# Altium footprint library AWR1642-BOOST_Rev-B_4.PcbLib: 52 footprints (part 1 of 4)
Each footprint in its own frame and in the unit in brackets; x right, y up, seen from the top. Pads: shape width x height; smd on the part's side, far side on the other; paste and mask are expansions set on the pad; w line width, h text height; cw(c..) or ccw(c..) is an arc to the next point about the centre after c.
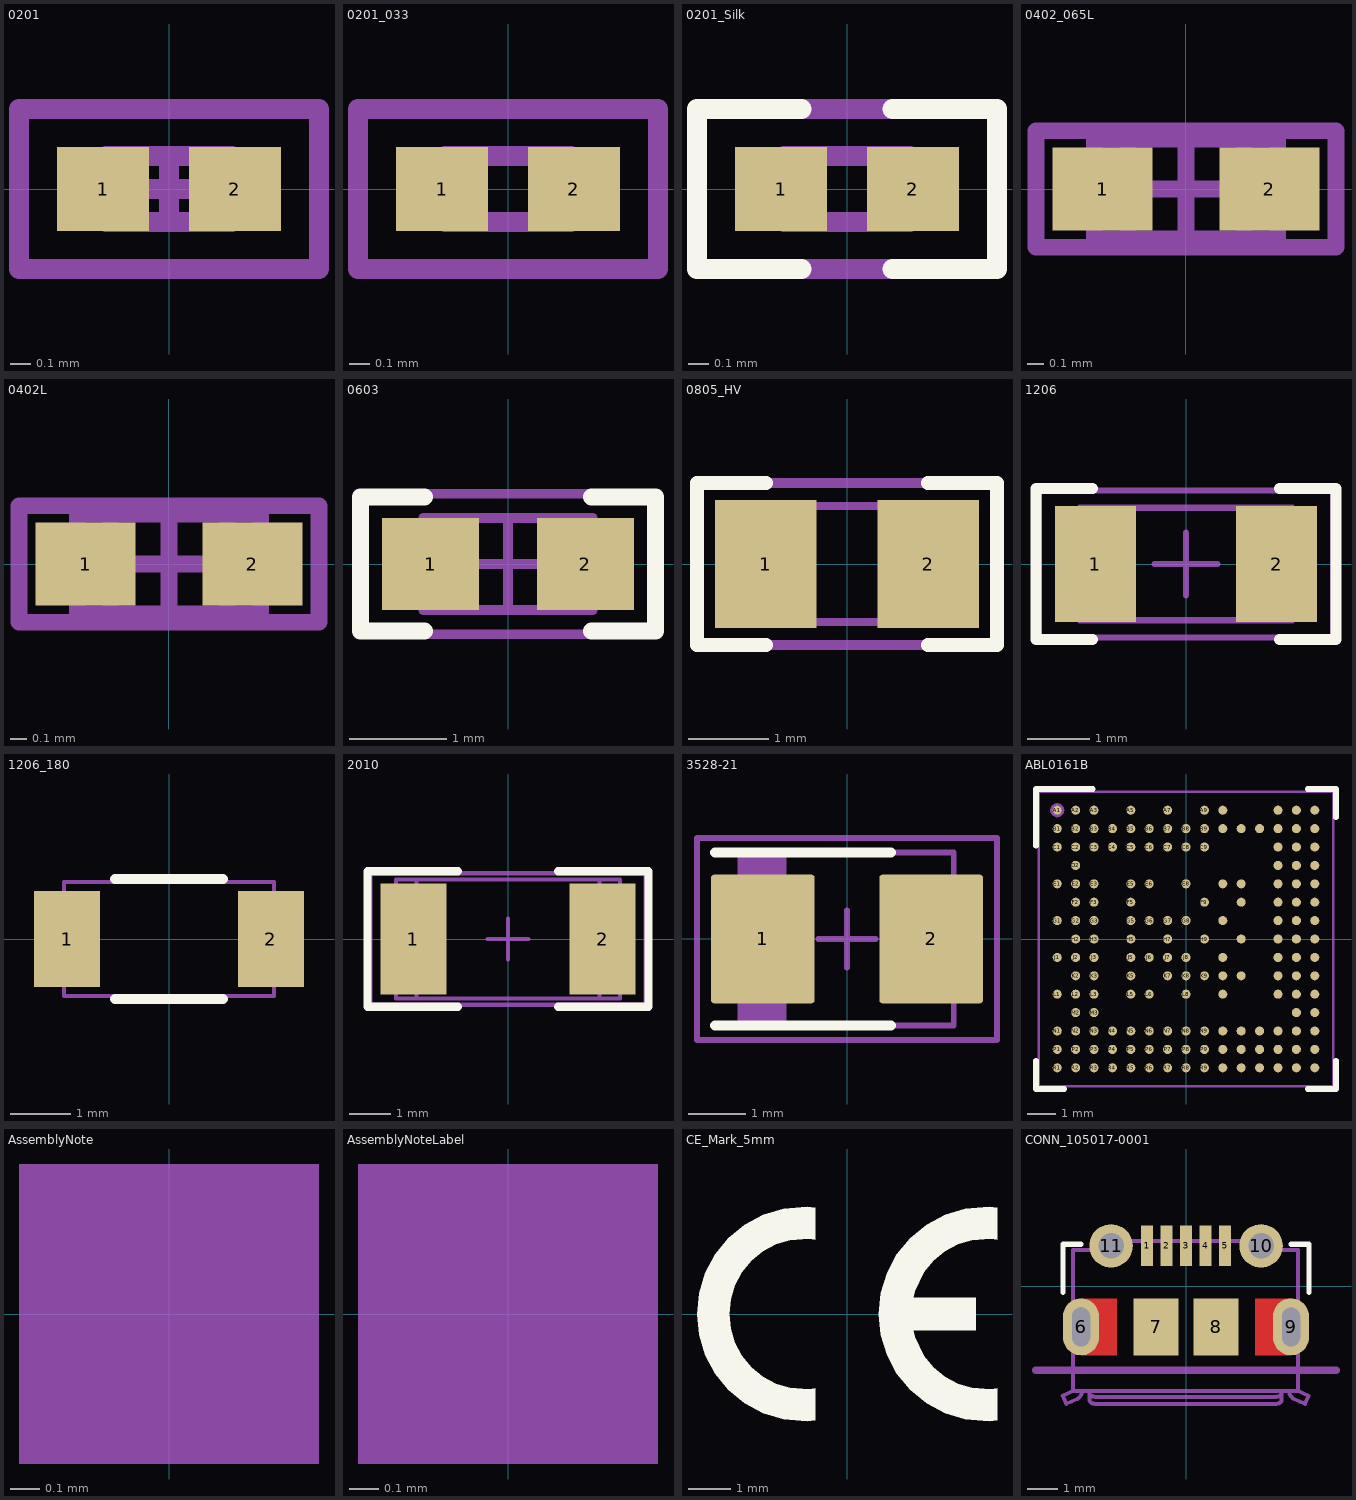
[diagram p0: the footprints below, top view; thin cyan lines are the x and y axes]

## 0201 [mm] "Data from Kemet datasheet CC101_COM dated 7/28/11"
height 0.26
pads (2):
  rect 0.46x0.42 smd mask+0.048: 1(-0.33,0) 2(0.33,0)
Mechanical 5:
  lines w0.1: -0.75,-0.4 -0.75,0.4 0.75,0.4 0.75,-0.4 -0.75,-0.4
  text ".Designator" at -0.66,-0.178 h0.36
Mechanical 13:
  lines w0.1: -0.215,-0.165 -0.215,0.165 ; 0.215,-0.165 0.215,0.165 ; -0.315,-0.165 0.315,-0.165 0.315,0.165 -0.315,0.165 -0.315,-0.165
Mechanical 15:
  lines w0.1: -0.165,0 0.165,0 ; 0,-0.165 0,0.165 ; -0.75,-0.4 0.75,-0.4 0.75,0.4 -0.75,0.4 -0.75,-0.4
3D body: height 0.26, standoff 0, extent 0.216,-0.164 0.314,0.164
3D body: height 0.26, standoff 0, extent -0.214,-0.164 0.214,0.164
3D body: height 0.26, standoff 0, extent -0.314,-0.164 -0.216,0.164

## 0201_033 [mm] "SMD, 2-Leads, Height 0.33mm"
height 0.33
pads (2):
  rect 0.46x0.42 smd mask+0: 1(-0.33,0) 2(0.33,0)
Mechanical 5:
  lines w0.1: -0.75,-0.4 -0.75,0.4 0.75,0.4 0.75,-0.4 -0.75,-0.4
  text ".Designator" at 0.644,0.219 h0.36
Mechanical 13:
  lines w0.1: -0.215,-0.165 -0.215,0.165 ; 0.215,-0.165 0.215,0.165 ; -0.315,-0.165 0.315,-0.165 0.315,0.165 -0.315,0.165 -0.315,-0.165
3D body: height 0.33, standoff 0, extent 0.216,-0.164 0.314,0.164
3D body: height 0.33, standoff 0, extent -0.214,-0.164 0.214,0.164
3D body: height 0.33, standoff 0, extent -0.314,-0.164 -0.216,0.164

## 0201_Silk [mm] "Data from Kemet datasheet CC101_COM dated 7/28/11"
height 0.26
pads (2):
  rect 0.46x0.42 smd mask+0: 1(-0.33,0) 2(0.33,0)
Top Overlay:
  lines w0.1: -0.229,-0.4 -0.75,-0.4 -0.75,0.4 -0.229,0.4 ; 0.229,-0.4 0.75,-0.4 0.75,0.4 0.229,0.4
Mechanical 5:
  lines w0.1: -0.75,-0.4 0.75,-0.4 0.75,0.4 -0.75,0.4 -0.75,-0.4
  text ".Designator" at 0.44,0.181 h0.36
Mechanical 13:
  lines w0.1: -0.215,-0.165 -0.215,0.165 ; 0.215,-0.165 0.215,0.165 ; -0.315,-0.165 -0.315,0.165 0.315,0.165 0.315,-0.165 -0.315,-0.165
3D body: height 0.26, standoff 0, extent -0.314,-0.164 -0.216,0.164
3D body: height 0.26, standoff 0, extent -0.214,-0.164 0.214,0.164
3D body: height 0.26, standoff 0, extent 0.216,-0.164 0.314,0.164

## 0402_065L [mm] "0402"
height 0.65
pads (2):
  rect 0.6x0.5 smd: 1(-0.5,0) 2(0.5,0)
Mechanical 5:
  lines w0.1: -0.9,-0.35 0.9,-0.35 0.9,0.35 -0.9,0.35 -0.9,-0.35
  text ".Designator" at 0.612,0.199 h0.43
Mechanical 13:
  lines w0.1: -0.35,-0.3 -0.35,0.3 ; 0.35,-0.3 0.35,0.3 ; -0.55,-0.3 -0.55,0.3 0.55,0.3 0.55,-0.3 -0.55,-0.3
Mechanical 15:
  lines w0.1: -0.3,0 0.3,0 ; 0,-0.3 0,0.3 ; -0.9,-0.35 -0.9,0.35 0.9,0.35 0.9,-0.35 -0.9,-0.35
3D body: height 0.65, standoff 0, extent -0.549,-0.299 -0.351,0.299
3D body: height 0.65, standoff 0, extent -0.349,-0.299 0.349,0.299
3D body: height 0.65, standoff 0, extent 0.351,-0.299 0.549,0.299

## 0402L [mm] "0402 from SM-752 data"
height 0.6
pads (2):
  rect 0.6x0.5 smd: 1(-0.5,0) 2(0.5,0)
Mechanical 5:
  lines w0.1: -0.9,-0.35 -0.9,0.35 0.9,0.35 0.9,-0.35 -0.9,-0.35
  text ".Designator" at -0.775,-0.225 h0.43
Mechanical 13:
  lines w0.1: -0.35,-0.3 -0.35,0.3 ; 0.35,-0.3 0.35,0.3 ; -0.55,-0.3 0.55,-0.3 0.55,0.3 -0.55,0.3 -0.55,-0.3
Mechanical 15:
  lines w0.1: -0.3,0 0.3,0 ; 0,-0.3 0,0.3 ; -0.9,-0.35 0.9,-0.35 0.9,0.35 -0.9,0.35 -0.9,-0.35
3D body: height 0.6, standoff 0, extent 0.351,-0.299 0.549,0.299
3D body: height 0.6, standoff 0, extent -0.349,-0.299 0.349,0.299
3D body: height 0.6, standoff 0, extent -0.549,-0.299 -0.351,0.299

## 0603 [mm] "0603 from SM-752 data"
height 1
pads (2):
  rect 1x0.95 smd: 1(-0.8,0) 2(0.8,0)
Top Overlay:
  lines w0.178: -0.864,-0.691 -1.524,-0.691 -1.524,0.693 -0.864,0.693 ; 0.864,-0.691 1.524,-0.691 1.524,0.693 0.864,0.693
Mechanical 5:
  lines w0.1: -1.55,-0.725 -1.55,0.725 1.55,0.725 1.55,-0.725 -1.55,-0.725
  text ".Designator" at -1.081,-0.401 h0.76
Mechanical 13:
  lines w0.1: -0.55,-0.475 -0.55,0.475 ; 0.55,-0.475 0.55,0.475 ; -0.875,-0.475 0.875,-0.475 0.875,0.475 -0.875,0.475 -0.875,-0.475
Mechanical 15:
  lines w0.1: -0.475,0 0.475,0 ; 0,-0.475 0,0.475 ; -1.55,-0.725 1.55,-0.725 1.55,0.725 -1.55,0.725 -1.55,-0.725
3D body: height 1, standoff 0, extent -0.874,-0.474 -0.551,0.474
3D body: height 1, standoff 0, extent -0.549,-0.474 0.549,0.474
3D body: height 1, standoff 0, extent 0.551,-0.474 0.874,0.474

## 0805_HV [mil] "0805 with 30mil clearance between pads"
height 57.09
pads (2):
  rect 50x63 smd: 1(-40,0) 2(40,0)
Top Overlay:
  lines w7: -40,-40 -74,-40 -74,0 -74,40 -40,40 ; 40,-40 74,-40 74,0 74,40 40,40
Mechanical 5:
  lines w5: -74,-40 74,-40 74,40 -74,40 -74,-40
  text ".Designator" at 33.84,16.51 h35
Mechanical 13:
  lines w3.94: -25.59,-28.54 -25.59,28.54 ; 25.59,-28.54 25.59,28.54 ; -43.31,-28.54 43.31,-28.54 43.31,28.54 -43.31,28.54 -43.31,-28.54
3D body: height 57.09, standoff 0, extent -43.29,-28.52 -25.61,28.52
3D body: height 57.09, standoff 0, extent -25.57,-28.52 25.57,28.52
3D body: height 57.09, standoff 0, extent 25.61,-28.52 43.29,28.52

## 1206 [mm] "1206 from SM-752 data"
height 1.35
pads (2):
  rect 1.3x1.85 smd: 1(-1.45,0) 2(1.45,0)
Top Overlay:
  lines w0.178: -1.5,-1.21 -2.4,-1.21 -2.4,1.21 -1.5,1.21 ; 1.5,-1.21 2.4,-1.21 2.4,1.21 1.5,1.21
Mechanical 5:
  lines w0.1: -1.7,-0.9 -1.7,0.9 1.7,0.9 1.7,-0.9 -1.7,-0.9
  text ".Designator" at 0.548,0.416 h0.81
Mechanical 13:
  lines w0.1: -1.2,-0.9 -1.2,0.9 ; 1.2,-0.9 1.2,0.9 ; -1.7,-0.9 -1.7,0.9 1.7,0.9 1.7,-0.9 -1.7,-0.9
Mechanical 15:
  lines w0.1: -0.5,0 0.5,0 ; 0,-0.5 0,0.5 ; -2.35,-1.175 -2.35,1.175 2.35,1.175 2.35,-1.175 -2.35,-1.175
3D body: height 1.35, standoff 0, extent 1.201,-0.899 1.699,0.899
3D body: height 1.35, standoff 0, extent -1.199,-0.899 1.199,0.899
3D body: height 1.35, standoff 0, extent -1.699,-0.899 -1.201,0.899

## 1206_180 [mm] "1206_180"
height 1.8
pads (2):
  rect 1.1x1.6 smd: 1(-1.7,0) 2(1.7,0)
Top Overlay:
  lines w0.17: -0.9,-1 0.9,-1 ; -0.9,1 0.9,1
Mechanical 5:
  lines w0.07: -1.75,-0.95 1.75,-0.95 1.75,0.95 -1.75,0.95 -1.75,-0.95
  text ".Designator" at 1.04,0.497 h0.81
3D body: height 1.8, standoff 0, extent -1.749,-0.949 -1.301,0.949
3D body: height 1.8, standoff 0, extent -1.299,-0.949 1.299,0.949
3D body: height 1.8, standoff 0, extent 1.301,-0.949 1.749,0.949

## 2010 [mm] "Chip Capacitor, Body 5.08x2.54mm, IPC Medium Density"
height 1.66
pads (2):
  rect 1.6x2.7 smd: 1(-2.3,0) 2(2.3,0)
Top Overlay:
  lines w0.2: -1.219,-1.65 -3.419,-1.65 -3.419,1.65 -1.219,1.65 ; 1.219,-1.65 3.419,-1.65 3.419,1.65 1.219,1.65
Mechanical 5:
  lines w0.1: -2.73,-1.45 2.73,-1.45 2.73,1.45 -2.73,1.45 -2.73,-1.45
  text ".Designator" at -1.875,-0.5 h1.02
Mechanical 13:
  lines w0.1: -2.23,-1.45 -2.23,1.45 ; 2.23,-1.45 2.23,1.45 ; -2.73,-1.45 -2.73,1.45 2.73,1.45 2.73,-1.45 -2.73,-1.45
Mechanical 15:
  lines w0.1: -0.5,0 0.5,0 ; 0,-0.5 0,0.5 ; -3.35,-1.6 -3.35,1.6 3.35,1.6 3.35,-1.6 -3.35,-1.6
3D body: height 1.66, standoff 0, extent 2.231,-1.449 2.729,1.449
3D body: height 1.66, standoff 0, extent -2.229,-1.449 2.229,1.449
3D body: height 1.66, standoff 0, extent -2.729,-1.449 -2.231,1.449

## 3528-21 [mm] "Medium Density IPC, based on Kemet datasheet 2016-10-20"
height 2.1
pads (2):
  rrect6% 1.8x2.23 smd: 1(-1.46,0) 2(1.46,0)
Top Overlay:
  lines w0.178: -2.286,-1.5 0.762,-1.5 ; -2.286,1.5 0.762,1.5
Mechanical 5:
  rectangle: -1.849,-1.5 -1.099,1.5
  lines w0.1: -1.1,-1.5 -1.1,1.5 ; -1.85,-1.5 -1.85,1.5 1.85,1.5 1.85,-1.5 -1.85,-1.5
  text ".Designator" at 0.709,-0.914 h1.2
Mechanical 15:
  lines w0.1: -0.5,0 0.5,0 ; 0,-0.5 0,0.5 ; -2.6,-1.75 2.6,-1.75 2.6,1.75 -2.6,1.75 -2.6,-1.75
3D body: height 2.12, standoff 0.01, extent -1.85,-1.5 1.85,1.5

## ABL0161B [mm] "BGA, 161-Balls, Body 10.4x10.4mm, Pitch 0.65mm"
height 1.17
pads (161):
  round 0.32 smd: A1(-4.55,4.55) A2(-3.9,4.55) A3(-3.25,4.55) A5(-1.95,4.55) A7(-0.65,4.55) A9(0.65,4.55) A10(1.3,4.55) A13(3.25,4.55) A14(3.9,4.55) A15(4.55,4.55) B1(-4.55,3.9) B2(-3.9,3.9) B3(-3.25,3.9) B4(-2.6,3.9) B5(-1.95,3.9) B6(-1.3,3.9) B7(-0.65,3.9) B8(0,3.9) B9(0.65,3.9) B10(1.3,3.9) B11(1.95,3.9) B12(2.6,3.9) B13(3.25,3.9) B14(3.9,3.9) B15(4.55,3.9) C1(-4.55,3.25) C2(-3.9,3.25) C3(-3.25,3.25) C4(-2.6,3.25) C5(-1.95,3.25) C6(-1.3,3.25) C7(-0.65,3.25) C8(0,3.25) C9(0.65,3.25) C13(3.25,3.25) C14(3.9,3.25) C15(4.55,3.25) D2(-3.9,2.6) D13(3.25,2.6) D14(3.9,2.6) D15(4.55,2.6) E1(-4.55,1.95) E2(-3.9,1.95) E3(-3.25,1.95) E5(-1.95,1.95) E6(-1.3,1.95) E8(0,1.95) E10(1.3,1.95) E11(1.95,1.95) E13(3.25,1.95) E14(3.9,1.95) E15(4.55,1.95) F2(-3.9,1.3) F3(-3.25,1.3) F5(-1.95,1.3) F9(0.65,1.3) F11(1.95,1.3) F13(3.25,1.3) F14(3.9,1.3) F15(4.55,1.3) G1(-4.55,0.65) G2(-3.9,0.65) G3(-3.25,0.65) G5(-1.95,0.65) G6(-1.3,0.65) G7(-0.65,0.65) G8(0,0.65) G10(1.3,0.65) G13(3.25,0.65) G14(3.9,0.65) G15(4.55,0.65) H2(-3.9,0) H3(-3.25,0) H5(-1.95,0) H7(-0.65,0) H9(0.65,0) H11(1.95,0) H13(3.25,0) H14(3.9,0) H15(4.55,0) J1(-4.55,-0.65) J2(-3.9,-0.65) J3(-3.25,-0.65) J5(-1.95,-0.65) J6(-1.3,-0.65) J7(-0.65,-0.65) J8(0,-0.65) J10(1.3,-0.65) J13(3.25,-0.65) J14(3.9,-0.65) J15(4.55,-0.65) K2(-3.9,-1.3) K3(-3.25,-1.3) K5(-1.95,-1.3) K7(-0.65,-1.3) K8(0,-1.3) K9(0.65,-1.3) K10(1.3,-1.3) K11(1.95,-1.3) K13(3.25,-1.3) K14(3.9,-1.3) K15(4.55,-1.3) L1(-4.55,-1.95) L2(-3.9,-1.95) L3(-3.25,-1.95) L5(-1.95,-1.95) L6(-1.3,-1.95) L8(0,-1.95) L10(1.3,-1.95) L13(3.25,-1.95) L14(3.9,-1.95) L15(4.55,-1.95) M2(-3.9,-2.6) M3(-3.25,-2.6) M14(3.9,-2.6) M15(4.55,-2.6) N1(-4.55,-3.25) N2(-3.9,-3.25) N3(-3.25,-3.25) N4(-2.6,-3.25) N5(-1.95,-3.25) N6(-1.3,-3.25) N7(-0.65,-3.25) N8(0,-3.25) N9(0.65,-3.25) N10(1.3,-3.25) N11(1.95,-3.25) N12(2.6,-3.25) N13(3.25,-3.25) N14(3.9,-3.25) N15(4.55,-3.25) P1(-4.55,-3.9) P2(-3.9,-3.9) P3(-3.25,-3.9) P4(-2.6,-3.9) P5(-1.95,-3.9) P6(-1.3,-3.9) P7(-0.65,-3.9) P8(0,-3.9) P9(0.65,-3.9) P10(1.3,-3.9) P11(1.95,-3.9) P12(2.6,-3.9) P13(3.25,-3.9) P14(3.9,-3.9) P15(4.55,-3.9) R1(-4.55,-4.55) R2(-3.9,-4.55) R3(-3.25,-4.55) R4(-2.6,-4.55) R5(-1.95,-4.55) R6(-1.3,-4.55) R7(-0.65,-4.55) R8(0,-4.55) R9(0.65,-4.55) R10(1.3,-4.55) R11(1.95,-4.55) R12(2.6,-4.55) R13(3.25,-4.55) R14(3.9,-4.55) R15(4.55,-4.55)
Top Overlay:
  lines w0.2: -5.3,-4.3 -5.3,-5.3 -4.3,-5.3 ; -5.3,3.3 -5.3,5.3 -3.3,5.3 ; 4.3,-5.3 5.3,-5.3 5.3,-4.3 ; 4.3,5.3 5.3,5.3 5.3,4.3
Mechanical 5:
  circle w0.1: c-4.55,4.55 r0.2
  lines w0.1: -5.2,-5.2 5.2,-5.2 5.2,5.2 -5.2,5.2 -5.2,-5.2
  text ".Designator" at 1.457,-3.676 h1.02
3D body: height 0.62, standoff 0, extent -5.2,-5.2 5.2,5.2

## AssemblyNote [mm] "Assembly Note"
height 0.6
Mechanical 5:
  rectangle: -0.508,-0.508 0.508,0.508
  text ".Designator" at -0.505,3.856 h1.02
  text ".Comment" at -0.385,-1.348 h1.02

## AssemblyNoteLabel [mm] "Assembly Note for PCB Labels"
height 0.6
Mechanical 5:
  rectangle: -0.508,-0.508 0.508,0.508
  text "Install label in silkscreened box after final wash.  Text shall be 8 pt font.  Text shall be per the Label Table in the PDF schematic." at -0.37,-1.284 h1.02
  text ".Designator" at -0.611,3.791 h1.02

## CE_Mark_5mm [mm] "Minimum text height for CE Mark"
Top Overlay:
  region: 3.5,-1.732 3.353,-1.753 2.907,-1.725 2.577,-1.625 2.273,-1.462 2.007,-1.243 1.788,-0.977 1.576,-0.535 1.541,-0.375 3,-0.375 3,0.375 1.541,0.375 1.576,0.535 1.788,0.977 2.007,1.243 2.273,1.462 2.577,1.625 2.907,1.725 3.353,1.753 3.5,1.732 3.5,2.487 3.315,2.506 2.76,2.464 2.289,2.321 1.854,2.089 1.474,1.776 1.161,1.396 0.929,0.961 0.786,0.49 0.738,0 0.786,-0.49 0.929,-0.961 1.161,-1.396 1.474,-1.776 1.854,-2.089 2.289,-2.321 2.76,-2.464 3.315,-2.506 3.5,-2.487
  region: -0.75,-2.487 -0.935,-2.506 -1.49,-2.464 -1.961,-2.321 -2.396,-2.089 -2.776,-1.776 -3.089,-1.396 -3.321,-0.961 -3.464,-0.49 -3.512,0 -3.464,0.49 -3.321,0.961 -3.089,1.396 -2.776,1.776 -2.396,2.089 -1.961,2.321 -1.49,2.464 -0.935,2.506 -0.75,2.487 -0.75,1.732 -0.897,1.753 -1.343,1.725 -1.673,1.625 -1.977,1.462 -2.243,1.243 -2.462,0.977 -2.625,0.673 -2.725,0.343 -2.758,0 -2.725,-0.343 -2.625,-0.673 -2.462,-0.977 -2.243,-1.243 -1.977,-1.462 -1.673,-1.625 -1.343,-1.725 -0.897,-1.753 -0.75,-1.732

## CONN_105017-0001 [mm] "Molex Micro USB-B"
height 2.9
pads (11):
  rect 0.4x1.35 smd: 1(-1.3,1.35) 2(-0.65,1.35) 3(0,1.35) 4(0.65,1.35) 5(1.3,1.35)
  oval 1.2x1.9 hole 0.6 slot 1.3 at 90 deg: 6(-3.5,-1.35) 9(3.5,-1.35)
  rect 1.5x1.9 smd: 7(-1,-1.35) 8(1,-1.35)
  round 1.45 hole 0.85: 10(2.5,1.35) 11(-2.5,1.35)
Top Layer:
  rectangle: -3.5,-2.3 -2.3,-0.4
  region: 3.5,-0.4 2.3,-0.4 2.3,-2.3 3.5,-2.3
Top Overlay:
  lines w0.178: -4.1,-0.2 -4.1,1.4 -3.5,1.4 ; 3.5,1.4 4.1,1.4 4.1,-0.2
Top Paste:
  region: 3.2,-0.4 2.3,-0.4 2.3,-2.3 3.2,-2.3
  rectangle: -3.2,-2.3 -2.3,-0.4
Mechanical 1:
  lines w0.254: -5,-2.8 5,-2.8
Mechanical 5:
  drawing of 162 lines, arcs and shapes, not listed
  text ".Designator" at -1.25,-1.304 h1.02
3D body: height 2.72, standoff -0.58, extent -4.1,-3.93 4.1,1.5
